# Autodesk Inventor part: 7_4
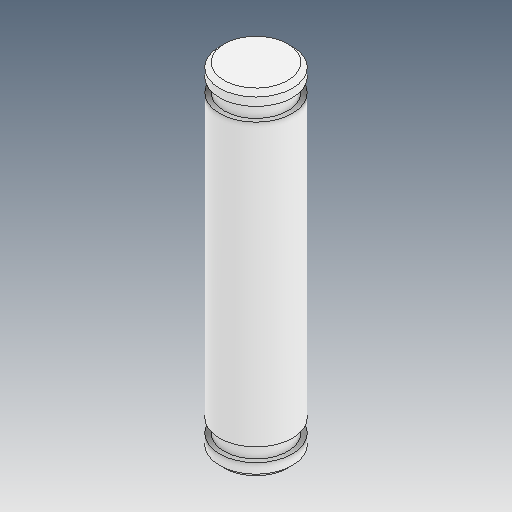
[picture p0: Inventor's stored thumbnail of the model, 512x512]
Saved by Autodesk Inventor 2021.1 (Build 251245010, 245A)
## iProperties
Created: 2021-06
Part Number: 7_4
Material: Ogólny
Document SubType Name: Modeling
Designer: user
Density: 1 g/cm^3
Appearance: Domyślna
Author: user
Revision Number: ÈÎºÎ
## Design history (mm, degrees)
feature "ÊäÈë1"
node "Bryła1"
